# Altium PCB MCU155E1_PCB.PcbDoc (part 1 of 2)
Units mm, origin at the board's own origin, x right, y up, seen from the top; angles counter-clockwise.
Board outline 32 x 29 mm, 4 copper layers (Top Layer, Layer 1, Layer 2, Bottom Layer), stack 1.567 mm thick; 102 components, 61 nets, 283 pads, 120 vias.
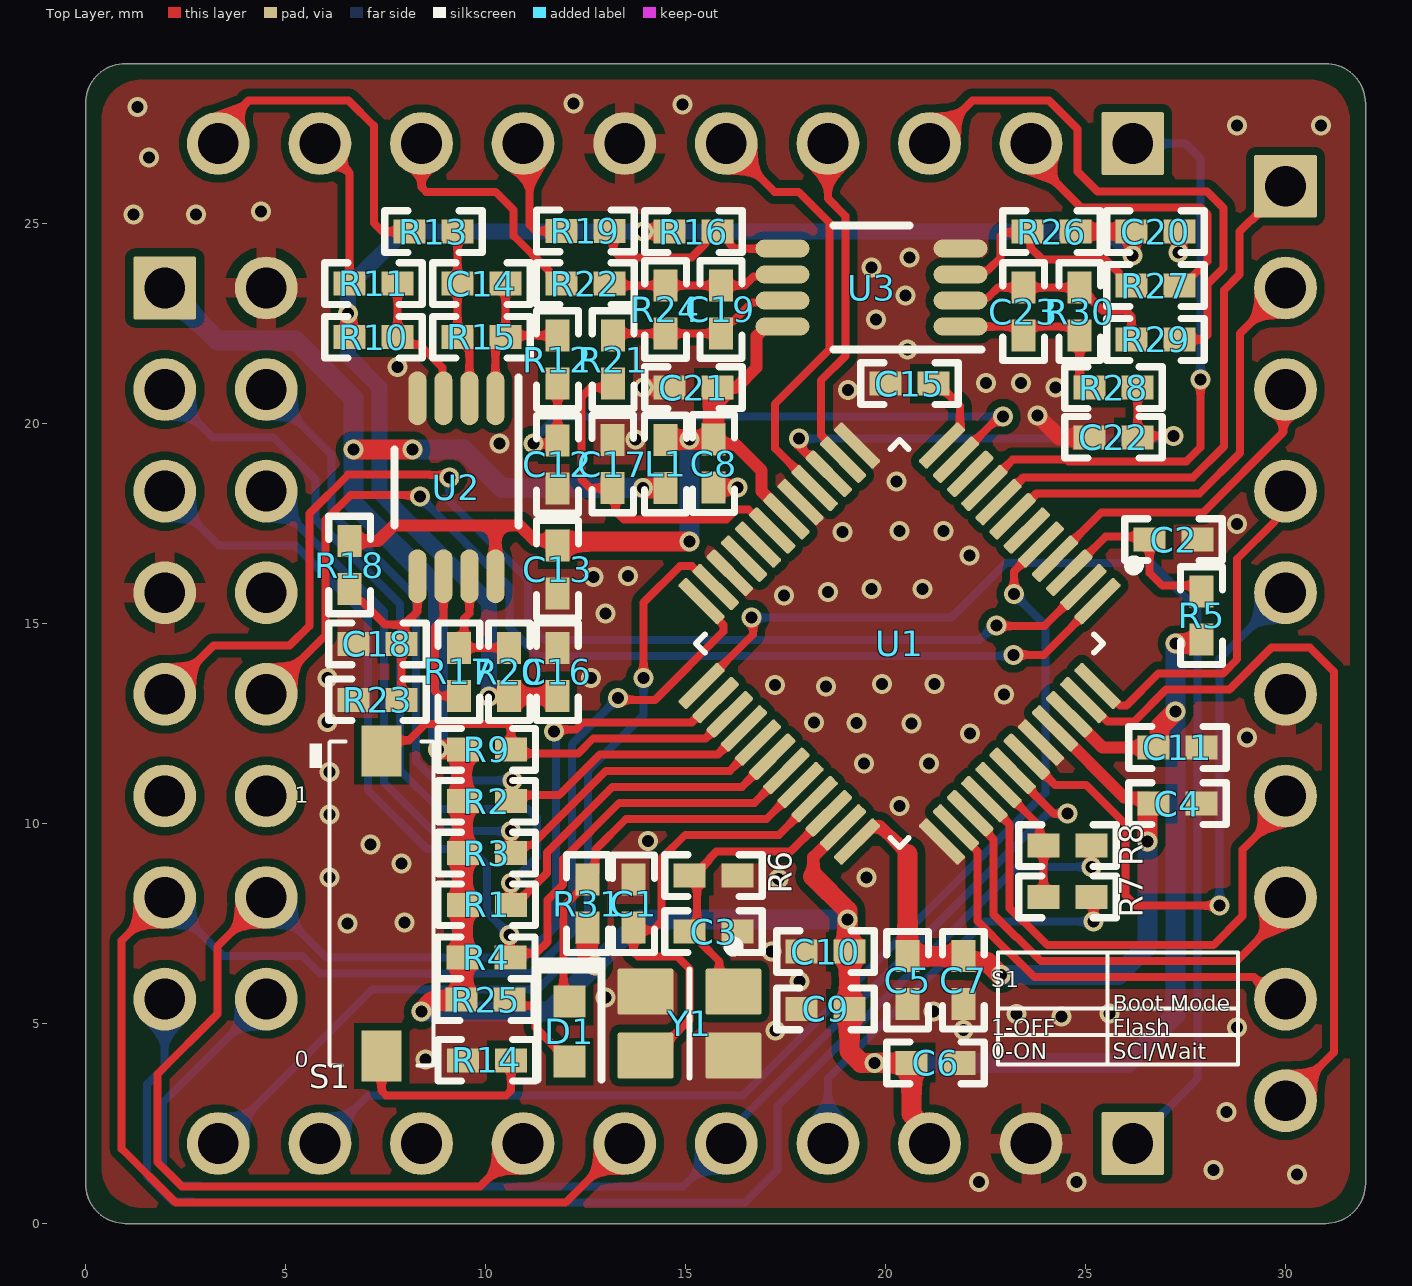
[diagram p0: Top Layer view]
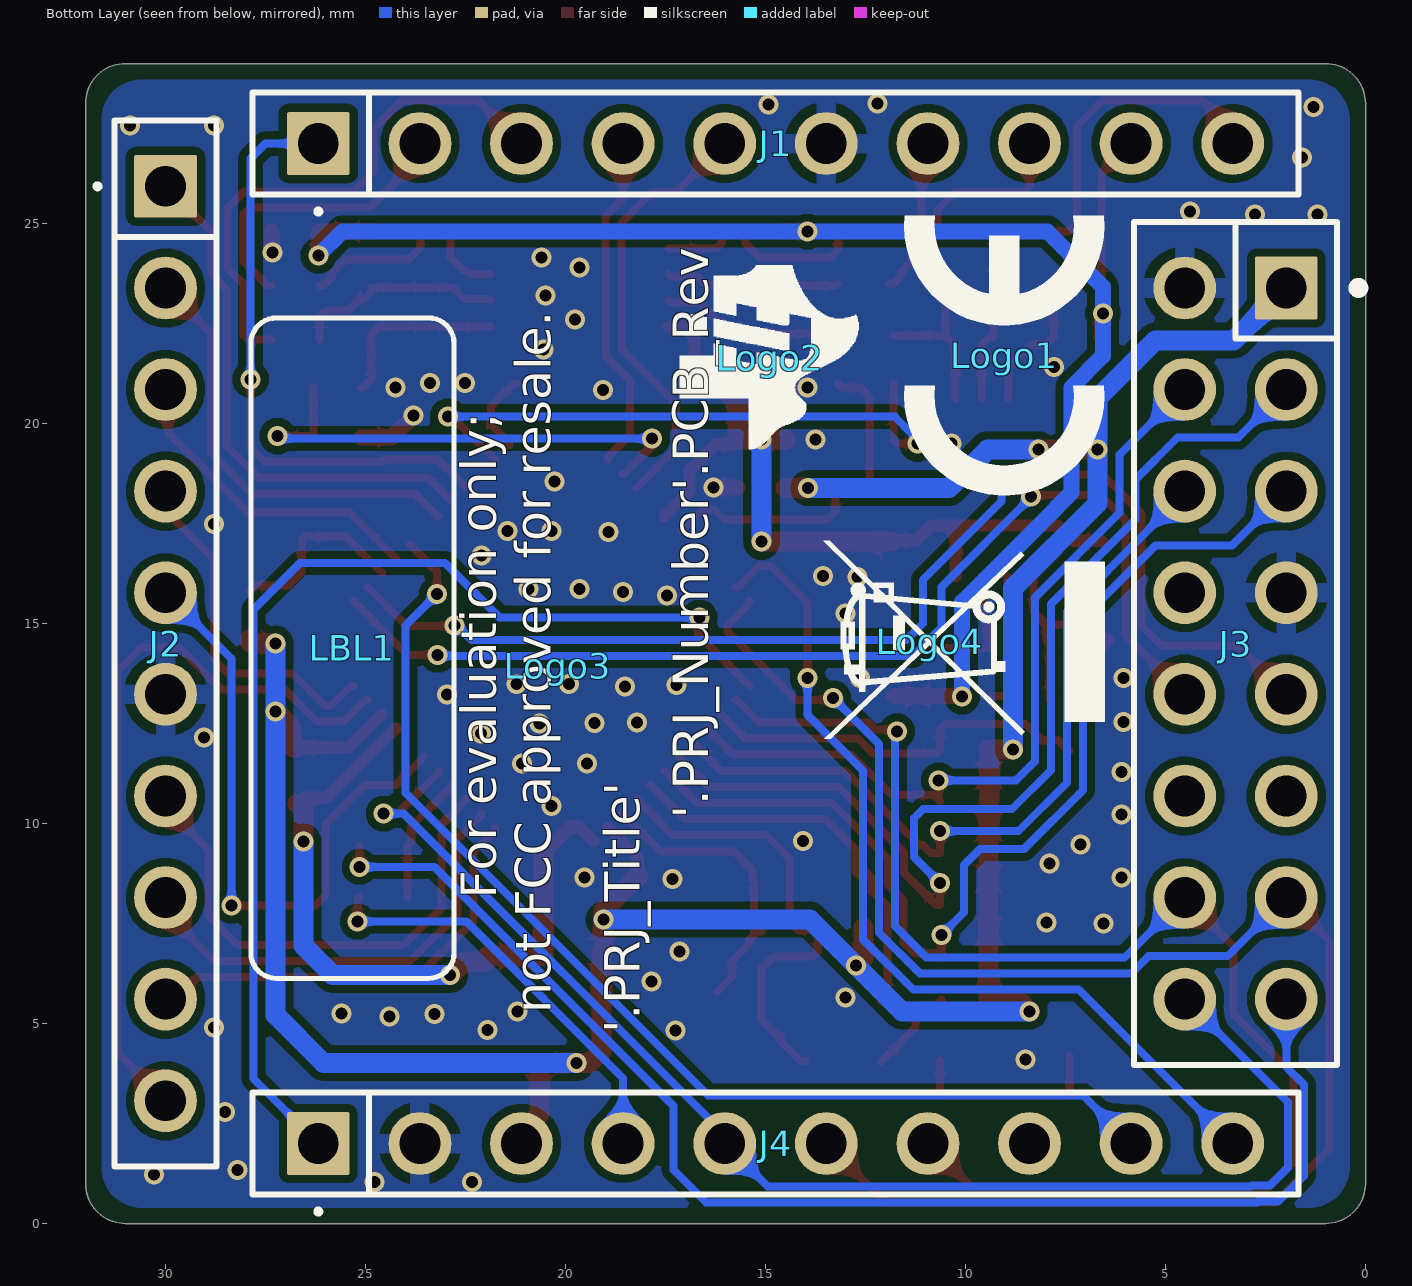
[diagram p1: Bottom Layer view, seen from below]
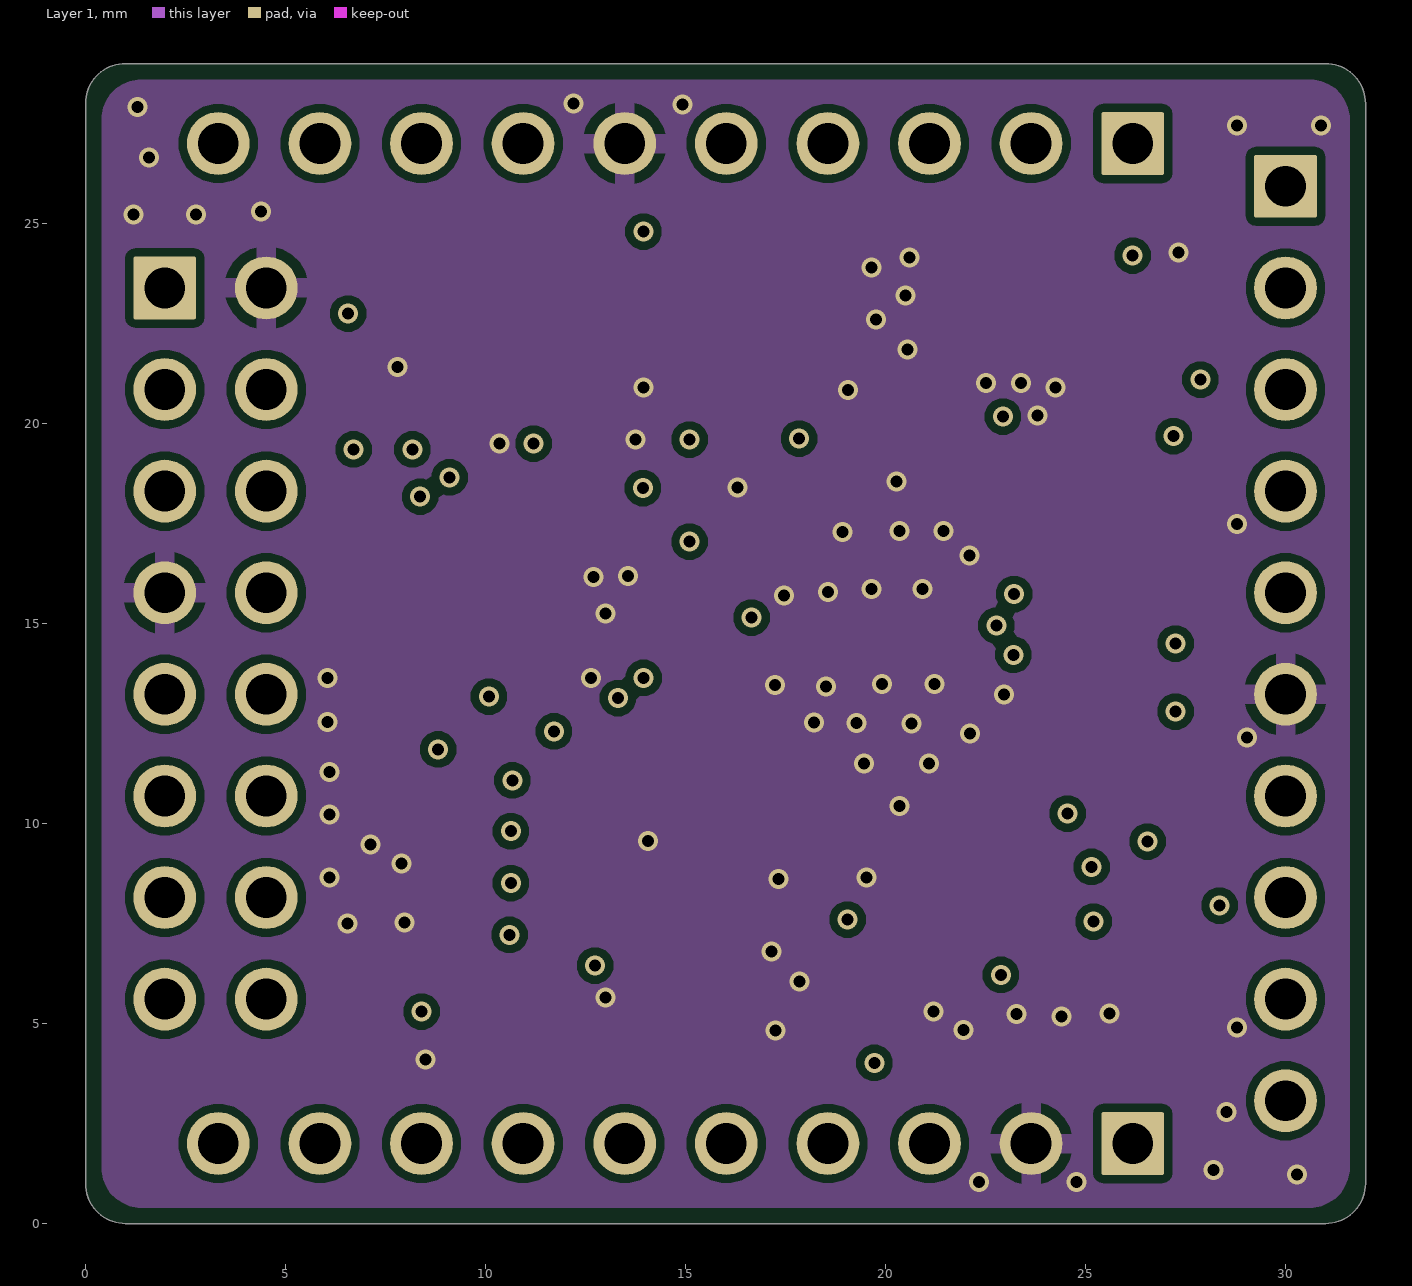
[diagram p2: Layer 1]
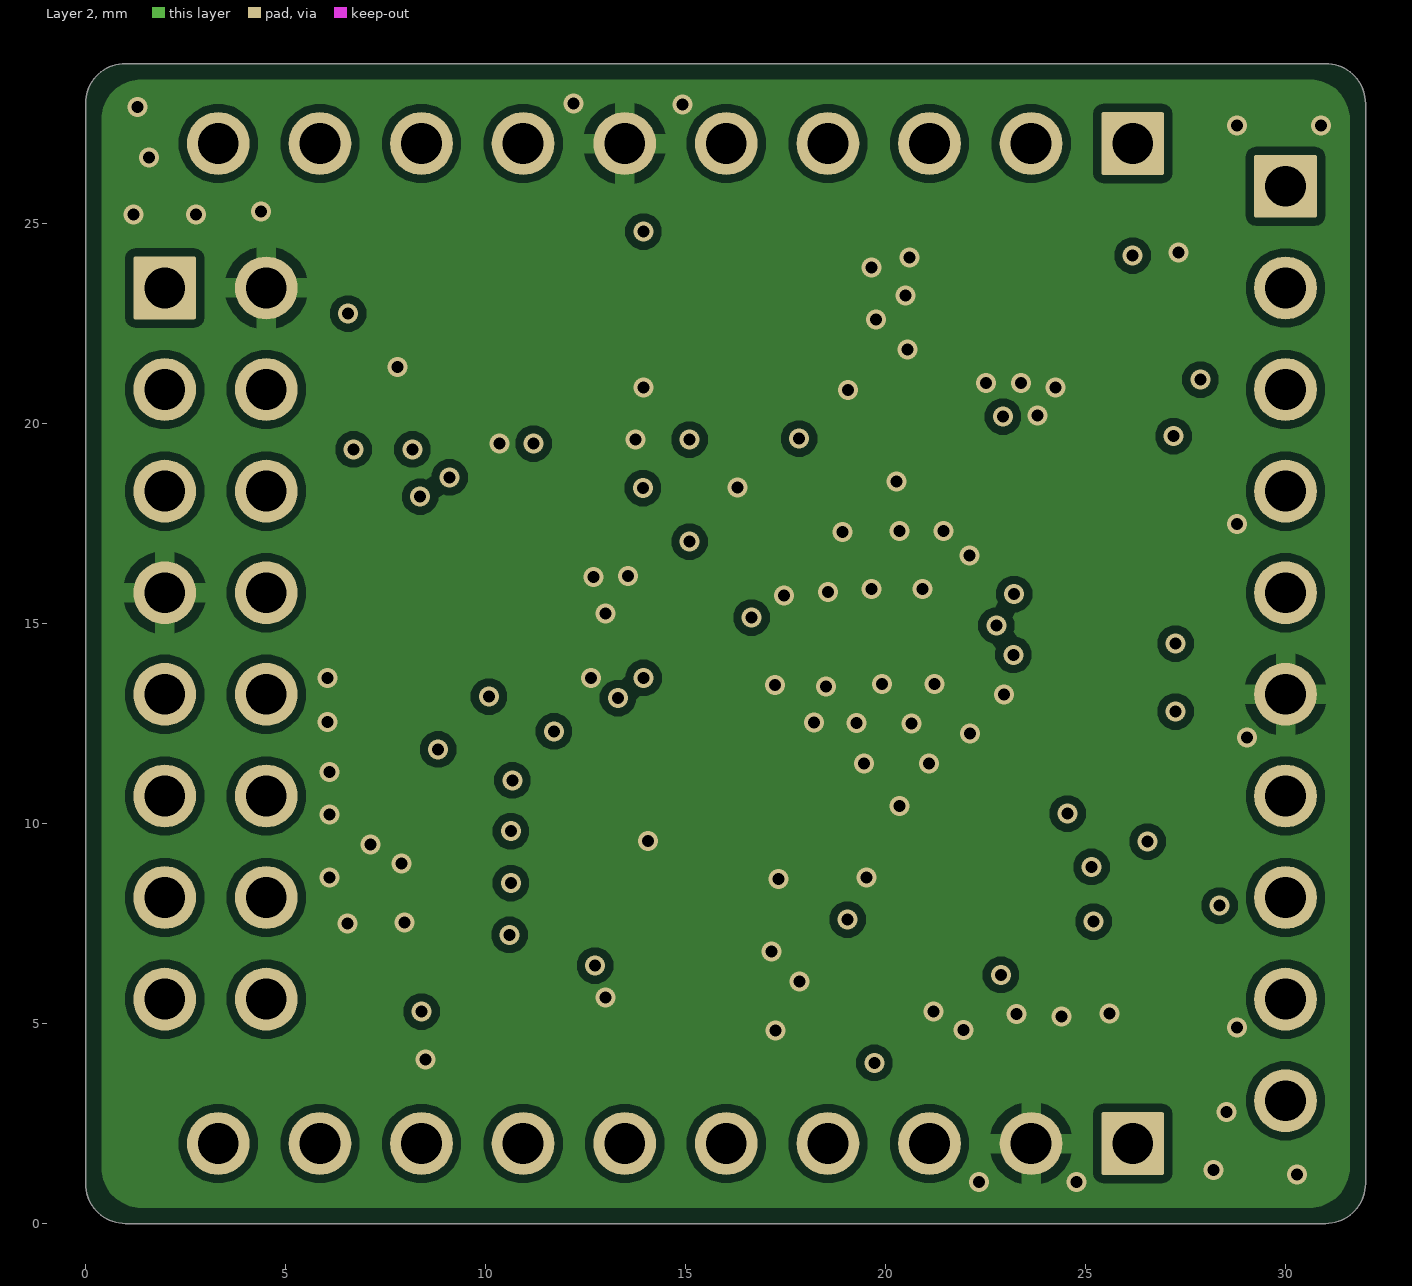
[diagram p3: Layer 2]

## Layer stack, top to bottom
Top Solder: solder mask 0.0102, Solder Resist, Dk 3.5
Top Layer: signal copper 0.035
Dielectric 1: prepreg 0.2184, PP-023, Dk 4.5
Layer 1: signal copper 0.035
Dielectric1: core 0.9906, Core-042, Dk 4.6
Layer 2: signal copper 0.035
Dielectric 2: prepreg 0.2184, PP-023, Dk 4.5
Bottom Layer: signal copper 0.035
Bottom Solder: solder mask 0.0102, Solder Resist, Dk 3.5

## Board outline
0,1 0,28 cw(c1,28) 1,29 31,29 cw(c31,28) 32,28 32,1 cw(c31,1) 31,0 1,0 cw(c1,1)

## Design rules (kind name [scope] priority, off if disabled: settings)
AcuteAngle [All] p1: minimum=4.50000000000000E+0001 checktracksonly=FALSE
AssemblyTestPointUsage [All] p1: valid=2
BoardOutlineClearance BoardOutlineClearance_MountingHoles [OnCopper and InComponentClass('Mounting Holes')] p1: gap=0 ignorepadtopadclearanceinfootprint=FALSE
BoardOutlineClearance BoardOutlineClearance_Poly [OnCopper and IsPoly] p2: gap=0 ignorepadtopadclearanceinfootprint=FALSE
BoardOutlineClearance [OnCopper and Not InComponentClass('Logo') and not InComponentClass('FiducialMark') and not InRegion(1000,500,4000,800) and not InPoly] p3: gap=0 ignorepadtopadclearanceinfootprint=FALSE
Clearance Clearance_1 [(InComponent('J1') or InComponent('J2') or InComponent('J3') or InComponent('J4') ) and not HasFootprint('fiducial10-20')] p1: gap=0.19 ignorepadtopadclearanceinfootprint=TRUE
Clearance PB+ToPB- [InNetClass('HV') vs InNetClass('LV_Signal')] p2: gap=3 ignorepadtopadclearanceinfootprint=TRUE
Clearance PB-ToACN [InNetClass('LV Signal') vs InNetClass('ACN')] p3: gap=3 ignorepadtopadclearanceinfootprint=TRUE
Clearance ACLToACN [InNetClass('ACL') vs InNetClass('ACN')] p4: gap=2 ignorepadtopadclearanceinfootprint=FALSE
Clearance ISOToAll [InNetClass('Isolation') vs not InNetClass('Isolation')   and (not  OnLayer('Keep-Out Layer'))] p5: gap=6 ignorepadtopadclearanceinfootprint=TRUE
Clearance PB-ToACL [InNetClass('LV Signal') vs InNetClass('ACL')] p6: gap=3 ignorepadtopadclearanceinfootprint=TRUE
Clearance PB+ToACL [InNetClass('V_BUS') vs InNetClass('ACL')] p7: gap=3 ignorepadtopadclearanceinfootprint=TRUE
Clearance PB+ToACN [InNetClass('V_BUS') vs InNetClass('ACN')] p8: gap=1.5 ignorepadtopadclearanceinfootprint=TRUE
Clearance SMTPadToTHHole [not IsVia and OnLayer('Multi-Layer') and not InComponent('J1') and not InComponent('J2') and not InComponent('J3') and not InComponent('J4') and not InComponent('J12') and PadIsPlated vs InSMTComponent and OnLayer('Bottom Layer') and not HasFootprint('TP_SM_1MM')] p9: gap=0.15 ignorepadtopadclearanceinfootprint=FALSE except(3: SMDPad-THPad)
Clearance [All vs not HasFootprint('fiducial10-20') or (InComponent('J1') or InComponent('J2') or InComponent('J3') or InComponent('J4') )] p10: gap=0.2 ignorepadtopadclearanceinfootprint=TRUE
ComponentClearance ComponentClearance_MountingHoles_FiducialMarks [InComponentClass('Mounting Holes') vs InComponentClass('FiducialMark')] p1: gap=1.27 collisioncheckmode=3 verticalgap=0.254 showdistances=FALSE
ComponentClearance ComponentClearance_Shunt [InComponentClass('Header') vs InComponentClass('Shunt')] p2: gap=0 collisioncheckmode=3 verticalgap=0 showdistances=FALSE
ComponentClearance ComponentClearance_Logo [InComponentClass('Logo')] p3: gap=0.762 collisioncheckmode=3 verticalgap=0.254 showdistances=FALSE
ComponentClearance ComponentClearance_ScrewToNut [(HasFootprint('NY PMS 440 0025 PH')) vs (HasFootprint('Keystone_1902C'))] p4: gap=0.127 collisioncheckmode=3 verticalgap=0.254 showdistances=FALSE
ComponentClearance ComponentClearance_MountingHoles [InComponentClass('Mounting Holes')] p5: gap=2.54 collisioncheckmode=3 verticalgap=2540 showdistances=FALSE
ComponentClearance ComponentClearance_SmallPassives [HasFootprint('0201*') or HasFootprint('0402*') or HasFootprint('0508') or HasFootprint('0603*') or HasFootprint('0612') or HasFootprint('0805*') or HasFootprint('0815*') or HasFootprint('0830*') or HasFootprint('1206*') or HasFootprint('1210*') or HasFootprint('1808*') or HasFootprint('1812*') or HasFootprint('1825*') or HasFootprint('2010*') or HasFootprint('2220*') or HasFootprint('2225*') or HasFootprint('2512*') or HasFootprint('2728*') or HasFootprint('3518*') vs HasFootprint('0201*') or HasFootprint('0402*') or HasFootprint('0508') or HasFootprint('0603*') or HasFootprint('0612') or HasFootprint('0805*') or HasFootprint('0815*') or HasFootprint('0830*') or HasFootprint('1206*') or HasFootprint('1210*') or HasFootprint('1808*') or HasFootprint('1812*') or HasFootprint('1825*') or HasFootprint('2010*') or HasFootprint('2220*') or HasFootprint('2225*') or HasFootprint('2512*') or HasFootprint('2728*') or HasFootprint('3518*')] p6: gap=0.38 collisioncheckmode=3 verticalgap=0.254 showdistances=FALSE
ComponentClearance ComponentClearance_THtoSMT [IsThruComponent vs IsSMTComponent] p7: gap=0.762 collisioncheckmode=3 verticalgap=0.762 showdistances=FALSE
ComponentClearance ComponentClearance_THtoTH [IsThruComponent vs IsThruComponent] p8: gap=0.508 collisioncheckmode=3 verticalgap=0.762 showdistances=FALSE
ComponentClearance [All] p9: gap=0.508 collisioncheckmode=3 verticalgap=0.254 showdistances=FALSE
DiffPairsRouting [All] p1: maxlimit=2.54 minlimit=0.254 mostfreqgap=0.254 toplayer_minwidth=0.381 toplayer_maxwidth=0.381 toplayer_prefwidth=0.381 midlayer1_minwidth=0.381 midlayer1_maxwidth=0.381 midlayer1_prefwidth=0.381 midlayer2_minwidth=0.381 midlayer2_maxwidth=0.381 midlayer2_prefwidth=0.381 bottomlayer_minwidth=0.381 bottomlayer_maxwidth=0.381 bottomlayer_prefwidth=0.381 maxuncoupledlength=25.4
FabricationTestPointUsage TestPointUsage [All] p1: valid=2 allowmultiple=FALSE
FabricationTestpoint Testpoint [All] p1: side=3 testpointundercomponent=TRUE minsize=1.016 maxsize=2.54 preferedsize=1.524 minholesize=0 maxholesize=1.016 preferedholesize=0.813 testpointgrid=0.025 allowsidetop=TRUE allowsidebottom=TRUE usegrid=TRUE gridtolerance=0
FanoutControl Fanout_LCC [IsLCC] p1: bgadir=Out bgaviamode=Centered fanoutstyle=Auto fanoutdirection=Alternating viagrid=0.025 // Fanout_LCC (Default Rule)
FanoutControl Fanout_BGA [IsBGA] p2: bgadir=Out bgaviamode=Centered fanoutstyle=Auto fanoutdirection=Alternating viagrid=0.025 // Fanout_BGA (Default Rule)
FanoutControl Fanout_Default [All] p4: bgadir=Out bgaviamode=Centered fanoutstyle=Auto fanoutdirection=Alternating viagrid=0.025 // Fanout_Default (Default Rule)
FanoutControl Fanout_Small [(CompPinCount < 5)] p5: bgadir=Out bgaviamode=Centered fanoutstyle=Auto fanoutdirection=OutThenIn viagrid=0.025 // Fanout_Small (Default Rule)
HoleSize [All] p1: absolutevalues=TRUE maxlimit=6.375 minlimit=0.2 maxpercent=80.000 minpercent=20.000
MinimumAnnularRing MinimumAnnularRing_ThermalPadVias [IsVia and InAnyComponent] p1: minimumring=0.15
MinimumAnnularRing [All] p2: minimumring=0.2
MinimumSolderMaskSliver MinimumSolderMaskSliver_Logo [InComponentClass('Logo') vs InComponentClass('Logo')] p1: minsoldermaskwidth=0.018
MinimumSolderMaskSliver [All] p2: minsoldermaskwidth=0.1
PlaneConnect [All] p1: planeconnectstyle=Direct reliefexpansion=0.254 reliefentries=4 reliefconductorwidth=0.254 reliefairgap=0.254
PolygonConnect "Thermal relief" [All vs InNet('GND') or innet('GND_ISO')  or innet('ubus')] p1: thpad.connectstyle=Relief thpad.reliefconductorwidth=0.5 thpad.reliefentries=4 thpad.polygonreliefangle="90 Angle" thpad.airgapwidth=0.254 smdpad.connectstyle=Direct smdpad.reliefconductorwidth=0.5 smdpad.reliefentries=4 smdpad.polygonreliefangle="90 Angle" smdpad.airgapwidth=0.254 via.connectstyle=Direct via.reliefconductorwidth=0.5 via.reliefentries=4 via.polygonreliefangle="90 Angle" via.airgapwidth=0.254
PolygonConnect [All] p2: connectstyle=Direct reliefconductorwidth=0.254 reliefentries=4 polygonreliefangle="90 Angle" airgapwidth=0.254
RoutingVias ThermalPadVias [IsVia and InAnyComponent] p1: holewidth=0.2 width=0.5 viastyle="Through Hole" minholewidth=0.2 minwidth=0.5 maxholewidth=0.33 maxwidth=0.6
RoutingVias [All] p2: holewidth=0.2 width=0.5 viastyle="Through Hole" minholewidth=0.2 minwidth=0.4 maxholewidth=1 maxwidth=1.4
SilkToBoardRegionClearance [Not ((IsComment or IsDesignator) And (Hide <> 'False')) and not InRegion(1000,500,4000,800)] p1:
SilkToSilkClearance SilkToSilkClearance_Pb-FreeLogo [(HasFootprint('Pb-Free_Overlay_Medium') OR HasFootprint('Pb-Free_Overlay_Small')) vs (HasFootprint('Pb-Free_Overlay_Medium') OR HasFootprint('Pb-Free_Overlay_Small'))] p1: silktosilkclearance=0
SilkToSilkClearance [All] p2: silktosilkclearance=0.1
SilkToSolderMaskClearance SilkToComponentPadClearance [(IsPad or IsFill or IsRegion) and InAnycomponent] p1: minsilkscreentomaskgap=0.127 clearancetoexposedcopper=TRUE
SilkToSolderMaskClearance "Silk to Solder Mask Opening" [All] p2: minsilkscreentomaskgap=0.1 clearancetoexposedcopper=FALSE
SolderMaskExpansion [All] p1: expansion=0.05 istentingtop=FALSE
UnRoutedNet [All] p1: checkbadconnections=TRUE
Width [All] p1: maxlimit=5 minlimit=0.2 preferedwidth=0.3 minimp=50.000000 maximp=50.000000 favimp=50.000000 checkconnectedcopper=TRUE
14 further rules are at their usual default settings.

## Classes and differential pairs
component class Logo: Logo2
component class Label: LBL1
component class TIEVM-MC-MODULE-F280013x: C1 C2 C3 C4 C5 C6 C7 C8 C9 C10 C11 C12 C13 C14 C15 C16 C17 C18 C19 C20 C21 C22 C23 D1 J1 J2 J3 J4 L1 LBL1 Logo1 Logo2 Logo3 Logo4 R1 R2 R3 R4 R5 R6 R7 R8 R9 R10 R11 R12 R13 R14 R15 R16 R17 R18 R19 R20 R21 R22 R23 R24 R25 R26 R27 R28 R29 R30 R31 S1 U1 U2 U3 Y1

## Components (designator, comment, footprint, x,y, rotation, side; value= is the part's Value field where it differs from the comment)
C1 "GRM1555C1H120JA01D" 0402 13.7,7.998 r270 top value=12pF
C2 "GRM155R71C104KA88D" 0402 27.2,17.1 r0 top value=0.1uF
C3 "GRM1555C1H120JA01D" 0402 15.7,7.3 r0 top value=12pF
C4 "GRM155R71C104KA88D" 0402 27.3,10.5 r180 top value=0.1uF
C5 "GRM155R71C104KA88D" 0402 20.551,6.083 r90 top value=0.1uF
C6 "GRM155R61A106ME11" 0402 21.25,4.015 r0 top value=10uF
C7 "GRM155R61A106ME11" 0402 21.948,6.083 r90 top value=10uF
C8 "GRM155R61A106ME11" 0402 15.7,19 r270 top value=10uF
C9 "GRM155R61A106ME11" 0402 18.5,5.366 r180 top value=10uF
C10 "GRM155R71C104KA88D" 0402 18.5,6.8 r180 top value=0.1uF
C11 "GRM155R71C104KA88D" 0402 27.3,11.901 r0 top value=0.1uF
C12 "C1005C0G1H221F050BA" 0402 11.8,18.977 r270 top value=220pF
C13 "GRM155R71C104KA88D" 0402 11.8,16.353 r270 top value=0.1uF
C14 "GRM1555C1H101JA01D" 0402 9.9,23.5 r0 top value=100pF
C15 "GRM155R61A225ME95" 0402 20.6,21 r180 top value=2.2uF
C16 "GRM155R61C103KA01D" 0402 11.799,13.793 r90 top value=0.01uF
C17 "C1005C0G1H221F050BA" 0402 13.18,18.988 r90 top value=220pF
C18 "GRM155R71C104KA88D" 0402 7.299,14.491 r180 top value=0.1uF
C19 "GRM1555C1H101JA01D" 0402 15.887,22.852 r270 top value=100pF
C20 "GRM155R71C104KA88D" 0402 26.75,24.8 r0 top value=0.1uF
C21 "GRM155R71C104KA88D" 0402 15.2,20.9 r180 top value=0.1uF
C22 "C1005C0G1H221F050BA" 0402 25.7,19.656 r180 top value=220pF
C23 "GRM1555C1H101JA01D" 0402 23.451,22.8 r270 top value=100pF
D1 "LTST-C193KRKT-5A" LTST-C193_Red 12.1,4.8 r90 top value=Red
J1 "SSQ-110-03-T-S" FP-SSQ-110-03-T-S_CONN_RCPT10-MFG 14.75,27 r180 bottom
J2 "SSQ-110-03-T-S" FP-SSQ-110-03-T-S_CONN_RCPT10-MFG 30,14.5 r270 bottom locked
J3 "SSQ-108-03-T-D" FP-SSQ-108-03-T-D_HDR16-MFG 3.25,14.5 r270 bottom locked
J4 "SSQ-110-03-T-S" FP-SSQ-110-03-T-S_CONN_RCPT10-MFG 14.75,2 r180 bottom locked
L1 "782423100" 0402 14.5,18.988 r90 top value="10 ohm"
LBL1 "THT-14-423-10" Label_650x200 25.326,14.385 r270 bottom
Logo1 "CE Mark" CE_Mark_5mm 9.033,21.7 r90 bottom
Logo2 "Texas Instruments" TI_Symbol_Overlay_Small 14.9,21.65 r90 bottom
Logo3 "FCC disclaimer" FCC_disclaimer_stacked 20.2,13.95 r90 bottom
Logo4 "WEEE logo" WEEE_Minimum 10.9,14.55 r90 bottom
M44 "Comment" Arrow 375.549,113.9 r0 top
M45 "Comment" Arrow 418.549,113.9 r180 bottom
M46 "Comment" MARK 448.049,-5.6 r0 top
M47 "Comment" Toolinghole 433.049,-7.1 r0 top
M48 "Comment" "White oil-26X4" 354.049,111.9 r0 top
M49 "Comment" "Bad Mark" 418.049,-5.6 r0 top
M49 "Comment" MARK 443.049,-5.6 r0 top
M49_1 "Comment" "Bad Mark" 386.049,-5.6 r0 top
M49_2 "Comment" "Bad Mark" 354.049,-5.6 r0 top
M50 "Comment" MARK 298.049,-5.6 r0 top
M51 "Comment" MARK 298.049,112.4 r0 top
M52 "Comment" MARK 448.049,112.4 r0 top
M53 "Comment" Toolinghole 308.049,-7.1 r0 top
M54 "Comment" Toolinghole 308.049,113.9 r0 top
M55 "Comment" Toolinghole 438.049,113.9 r0 top
M56 "Comment" "Bad Mark" 413.049,-5.6 r0 top
M56_1 "Comment" "Bad Mark" 381.049,-5.6 r0 top
M56_2 "Comment" "Bad Mark" 349.049,-5.6 r0 top
M57 "Comment" "Bad Mark" 408.049,-5.6 r0 top
M57_1 "Comment" "Bad Mark" 376.049,-5.6 r0 top
M57_2 "Comment" "Bad Mark" 344.049,-5.6 r0 top
M57_2_1 "Comment" "Bad Mark" 334.049,-5.6 r0 top
M57_2_2 "Comment" "Bad Mark" 322.049,-5.6 r0 top
M58 "Comment" "Bad Mark" 403.049,-5.6 r0 top
M58_1 "Comment" "Bad Mark" 371.049,-5.6 r0 top
M58_2 "Comment" "Bad Mark" 339.049,-5.6 r0 top
M58_2_1 "Comment" "Bad Mark" 329.049,-5.6 r0 top
M59 "Comment" "Bad Mark" 398.049,-5.6 r0 top
M59_1 "Comment" "Bad Mark" 366.049,-5.6 r0 top
M60 "Comment" "Bad Mark" 393.049,-5.6 r0 top
M60_1 "Comment" "Bad Mark" 361.049,-5.6 r0 top
M61 "Comment" "Bad Mark" 425.049,-5.6 r0 top
R1 "ERJ-2RKF2401X" 0402 10.035,7.967 r180 top value=2.40k
R2 "RC0402FR-0710KL" 0402 10.035,10.557 r180 top value=10.0k
R3 "RC0402FR-0710KL" 0402 10.035,9.262 r180 top value=10.0k
R4 "RC0402FR-0710KL" 0402 10.019,6.647 r180 top value=10.0k
R5 "RC0402FR-0710KL" 0402 27.9,15.2 r270 top value=10.0k
R6 "RG1005P-104-B-T5" 0402 15.7,8.698 r180 top value=100k
R7 "RC0402JR-070RL" 0402 24.55,8.166 r180 top value=0
R8 "RC0402JR-070RL" 0402 24.55,9.45 r180 top value=0
R9 "CMP-0026949-3" 0402 10.035,11.852 r180 top value=56k
R10 "RC0402FR-0710KL" 0402 7.2,22.158 r180 top value=10.0k
R11 "ERJ-2RKF2401X" 0402 7.2,23.5 r0 top value=2.40k
R12 "RC0402FR-07100RL" 0402 11.8,21.6 r270 top value=100
R13 "ERJ-2RKF2401X" 0402 8.7,24.8 r0 top value=2.40k
R14 "CMP-0026890-5" 0402 10.035,4.082 r180 top value=2.2k
R15 "RC0402FR-0710KL" 0402 9.9,22.158 r0 top value=10.0k
R16 "RC0402FR-0710KL" 0402 15.2,24.8 r180 top value=10.0k
R17 "RC0402FR-0710KL" 0402 9.336,13.793 r270 top value=10.0k
R18 "RC0402FR-0710KL" 0402 6.6,16.463 r90 top value=10.0k
R19 "ERJ-2RKF2401X" 0402 12.498,24.814 r0 top value=2.40k
R20 "RC0402FR-07100RL" 0402 10.592,13.793 r270 top value=100
R21 "RC0402FR-07100RL" 0402 13.189,21.6 r270 top value=100
R22 "ERJ-2RKF2401X" 0402 12.498,23.5 r0 top value=2.40k
R23 "RC0402FR-0710KL" 0402 7.3,13.094 r0 top value=10.0k
R24 "RC0402FR-0710KL" 0402 14.501,22.852 r270 top value=10.0k
R25 "RC0402FR-071KL" 0402 10,5.6 r0 top value=1.00k
R26 "RC0402FR-0710KL" 0402 24.15,24.8 r0 top value=10.0k
R27 "ERJ-2RKF2401X" 0402 26.75,23.451 r180 top value=2.40k
R28 "RC0402FR-07100RL" 0402 25.7,20.9 r0 top value=100
R29 "ERJ-2RKF2401X" 0402 26.75,22.102 r180 top value=2.40k
R30 "RC0402FR-0710KL" 0402 24.853,22.8 r270 top value=10.0k
R31 "CMP-0026949-3" 0402 12.55,8 r270 top value=56k
S1 "CHS-01TB" SW_CHS-01TB 7.4,8 r0 top
U1 "F2800137PT" PT0048A-MFG 20.35,14.5 r225 top locked
U2 "TLV9062IDGKR" DGK0008A_N 9.273,18.406 r270 top
U3 "TLV9062IDGKR" DGK0008A_N 19.65,23.4 r180 top
Y1 "830108207209" FP-830108207209_SMT_CRYSTAL_3MM2_2MM5-MFG 15.1,5 r180 top

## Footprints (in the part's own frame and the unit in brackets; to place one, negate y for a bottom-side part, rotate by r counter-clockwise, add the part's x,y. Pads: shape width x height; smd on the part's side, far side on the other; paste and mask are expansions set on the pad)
0402 [mm] "0402 from SM-752 data"
  rect 0.8x0.6 smd: 1(-0.6,0) 2(0.6,0)
  silkscreen extent -1.22,-0.52 1.22,0.52, body extent -0.55,-0.3 0.55,0.3, height 0.6
Arrow [mm] "·½Ïò¼ýÍ·"
  silkscreen extent 0,-2 43,2
"Bad Mark" [mm]
  round 2 on Bottom Solder: 2(0,0)
  round 2 on Top Solder: 2(0,0)
  Top Layer pour cut-out: -1.051,0 -0.971,-0.402 -0.743,-0.743 -0.402,-0.971 0,-1.051 0,-1.051 0.402,-0.971 0.743,-0.743 0.971,-0.402 1.051,0 1.051,0 0.971,0.402 0.743,0.743 0.402,0.971 0,1.051 0,1.051 -0.402,0.971 -0.743,0.743 -0.971,0.402 -1.051,0
  Top Layer region: -0.5,-0.25 -0.5,0.25 0.5,0.25 0.5,-0.25
  Top Layer region: -0.25,0.5 0.25,0.5 0.25,-0.5 -0.25,-0.5
  Bottom Layer pour cut-out: 1.051,0 0.971,-0.402 0.743,-0.743 0.402,-0.971 0,-1.051 0,-1.051 -0.402,-0.971 -0.743,-0.743 -0.971,-0.402 -1.051,0 -1.051,0 -0.971,0.402 -0.743,0.743 -0.402,0.971 0,1.051 0,1.051 0.402,0.971 0.743,0.743 0.971,0.402 1.051,0
  Bottom Layer region: 0.25,0.5 -0.25,0.5 -0.25,-0.5 0.25,-0.5
  Bottom Layer region: 0.5,-0.25 0.5,0.25 -0.5,0.25 -0.5,-0.25
CE_Mark_5mm [mm] "Minimum text height for CE Mark"
  silkscreen extent -3.5,-2.5 3.5,2.5
DGK0008A_N [mm] "TSOP, 8-Leads, Body 3x3mm, Pitch 0.65mm, IPC Medium Density"
  oval 1.35x0.45 smd: 1(-2.225,0.975) 2(-2.225,0.325) 3(-2.225,-0.325) 4(-2.225,-0.975) 5(2.225,-0.975) 6(2.225,-0.325) 7(2.225,0.325) 8(2.225,0.975)
  silkscreen extent -2.75,-1.55 0.95,1.55, body extent -2.45,-1.5 2.45,1.5, height 0.96
FCC_disclaimer_stacked [mm]
FP-830108207209_SMT_CRYSTAL_3MM2_2MM5-MFG [mm]
  rrect9% 1.4x1.15 smd paste+0 mask+0: 1(-1.1,-0.8) 2(1.1,-0.8) 3(1.1,0.8) 4(-1.1,0.8)
  silkscreen extent -1.23,-2.05 0,1.35, body extent -1.9,-1.47 1.9,1.48, height 0.25
FP-SSQ-108-03-T-D_HDR16-MFG [mm]
  rrect6% 1.57x1.57 hole 1.02 paste+0 mask+0: 1(-8.89,1.27)
  round 1.57 hole 1.02 paste+0 mask+0: 2(-8.89,-1.27) 3(-6.35,1.27) 4(-6.35,-1.27) 5(-3.81,1.27) 6(-3.81,-1.27) 7(-1.27,1.27) 8(-1.27,-1.27) 9(1.27,1.27) 10(1.27,-1.27) 11(3.81,1.27) 12(3.81,-1.27) 13(6.35,1.27) 14(6.35,-1.27) 15(8.89,1.27) 16(8.89,-1.27)
  silkscreen extent -10.54,-2.54 10.54,3.19, body extent -10.42,-2.48 10.42,2.48, height 8.64
FP-SSQ-110-03-T-S_CONN_RCPT10-MFG [mm]
  rrect6% 1.57x1.57 hole 1.02 paste+0 mask+0: 1(-11.43,0)
  round 1.57 hole 1.02 paste+0 mask+0: 2(-8.89,0) 3(-6.35,0) 4(-3.81,0) 5(-1.27,0) 6(1.27,0) 7(3.81,0) 8(6.35,0) 9(8.89,0) 10(11.43,0)
  silkscreen extent -13.08,-1.76 13.08,1.27, body extent -12.95,-1.21 12.95,1.21, height 8.64
Label_650x200 [mil] "Thermal Transfer Label"
  round 1 on Mech14: 0(0,0)
  silkscreen extent -325,-100 325,100, body extent -325,-100 325,100, height 1
LTST-C193_Red [mm] "SMD, 2-Leads, Body1.6x0.8mm"
  rect 0.8x0.8 smd: 1(-0.75,0) 2(0.75,0)
  silkscreen extent -1.2,-0.9 1.85,0.9, body extent -0.85,-0.45 0.85,0.45, height 0.45
MARK [mm]
  round 1 smd mask+0.5: 1(0,0)
  round 1 smd far side mask+0.5: 2(0,0)
  Top Layer pour cut-out: -1.5,0 -1.386,-0.574 -1.061,-1.061 -0.574,-1.386 0,-1.5 0,-1.5 0.574,-1.386 1.061,-1.061 1.386,-0.574 1.5,0 1.5,0 1.386,0.574 1.061,1.061 0.574,1.386 0,1.5 0,1.5 -0.574,1.386 -1.061,1.061 -1.386,0.574 -1.5,0
  Bottom Layer pour cut-out: -1.5,0 -1.386,-0.574 -1.061,-1.061 -0.574,-1.386 0,-1.5 0,-1.5 0.574,-1.386 1.061,-1.061 1.386,-0.574 1.5,0 1.5,0 1.386,0.574 1.061,1.061 0.574,1.386 0,1.5 0,1.5 -0.574,1.386 -1.061,1.061 -1.386,0.574 -1.5,0
PT0048A-MFG [mm]
  rrect33% 1.4x0.3 smd paste-1000 mask+0: 1(-4.25,2.75) 2(-4.25,2.25) 3(-4.25,1.75) 4(-4.25,1.25) 5(-4.25,0.75) 6(-4.25,0.25) 7(-4.25,-0.25) 8(-4.25,-0.75) 9(-4.25,-1.25) 10(-4.25,-1.75) 11(-4.25,-2.25) 12(-4.25,-2.75) 25(4.25,-2.75) 26(4.25,-2.25) 27(4.25,-1.75) 28(4.25,-1.25) 29(4.25,-0.75) 30(4.25,-0.25) 31(4.25,0.25) 32(4.25,0.75) 33(4.25,1.25) 34(4.25,1.75) 35(4.25,2.25) 36(4.25,2.75)
  rrect33% 0.3x1.4 smd paste-1000 mask+0: 13(-2.75,-4.25) 14(-2.25,-4.25) 15(-1.75,-4.25) 16(-1.25,-4.25) 17(-0.75,-4.25) 18(-0.25,-4.25) 19(0.25,-4.25) 20(0.75,-4.25) 21(1.25,-4.25) 22(1.75,-4.25) 23(2.25,-4.25) 24(2.75,-4.25) 37(2.75,4.25) 38(2.25,4.25) 39(1.75,4.25) 40(1.25,4.25) 41(0.75,4.25) 42(0.25,4.25) 43(-0.25,4.25) 44(-0.75,4.25) 45(-1.25,4.25) 46(-1.75,4.25) 47(-2.25,4.25) 48(-2.75,4.25)
  silkscreen extent -5.65,-3.6 3.6,3.6, body extent -5.05,-5.05 5.05,5.05, height 0.25
SW_CHS-01TB [mm] "CHS Recommended footprint"
  rect 1x1.27 smd: 1(0,3.81) 2(0,-3.81)
  silkscreen extent -1.8,-4.05 1.3,4.05, body extent -1.25,-4 1.25,4, height 2.51
TI_Symbol_Overlay_Small [mm]
  silkscreen extent -2.3,-2.23 2.3,2.24
Toolinghole [mm]
  round 2 hole 2 unplated: 1(0,0)
  silkscreen extent -1.41,-1.41 1.41,1.41
WEEE_Minimum [mm] "WEEElie bin"
  silkscreen extent -2.42,-4.38 2.52,2.65
"White oil-26X4" [mm] "¶þÎ¬Âë°×ÓÍ¿ò"
  silkscreen extent -26,0 0,4

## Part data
C1 C3: library part CMP-0006415-2, "CAP, CERM, 12 pF, 50 V, +/- 5%, C0G/NP0, 0402", Cap_Case=0402, Manufacturer=MuRata, Supplier Part Number 1=14T3292, TempCo=C0G/NP0, Tolerance_%=5%, Value1=Unknown, Value2=50V, ValueDisplayed=12pF
C2 C4 C5 C10 C11 C13 C18 C20 C21: library part CMP-0006641-2, "CAP, CERM, 0.1 uF, 16 V, +/- 10%, X7R, 0402", Cap_Case=0402, Manufacturer=MuRata, Supplier Part Number 1=490-3261-1-ND, TempCo=X7R, Tolerance_%=10%, Value1=Unknown, Value2=16V, ValueDisplayed=0.1uF
C6 C7 C8 C9: library part CMP-0006564-1, "CAP, CERM, 10 uF, 10 V, +/- 20%, X5R, 0402", Cap_Case=0402, Manufacturer=MuRata, TempCo=X5R, Tolerance_%=20%, Value1=Unknown, Value2=10V, ValueDisplayed=10uF
C12 C17 C22: library part CMP-0006249-2, "CAP, CERM, 220 pF, 50 V, +/- 1%, C0G/NP0, 0402", Cap_Case=0402, Manufacturer=TDK, Supplier Part Number 1=445-7015-1-ND, TempCo=C0G/NP0, Tolerance_%=1%, Value1=Unknown, Value2=50V, ValueDisplayed=220pF
C14 C19 C23: library part CMP-0006410-2, "CAP, CERM, 100 pF, 50 V, +/- 5%, C0G/NP0, 0402", Cap_Case=0402, Manufacturer=MuRata, Supplier Part Number 1=81-GRM1555C1H101JA1D, TempCo=C0G/NP0, Tolerance_%=5%, Value1=Unknown, Value2=50V, ValueDisplayed=100pF
C15: library part CMP-0006571-2, "CAP, CERM, 2.2 uF, 10 V, +/- 20%, X5R, 0402", Cap_Case=0402, Manufacturer=MuRata, Supplier Part Number 1=490-10452-1-ND, TempCo=X5R, Tolerance_%=20%, Value1=Unknown, Value2=10V, ValueDisplayed=2.2uF
C16: library part CMP-0006590-2, "CAP, CERM, 0.01 uF, 16 V, +/- 10%, X5R, 0402", Cap_Case=0402, Manufacturer=MuRata, Supplier Part Number 1=GRM155R61C103KA01D-ND, TempCo=X5R, Tolerance_%=10%, Value1=Unknown, Value2=16V, ValueDisplayed=0.01uF
D1: library part CMP-0079922-3, "LED, Red, SMD", Color=Red, Manufacturer=Lite-On, Value1=W, Value2=2V
J1 J2 J4: library part CMP-0123041-2, "Conn Socket Strip SKT 10 POS 2.54mm Solder ST Top Entry Thru-Hole Bulk", Current_A=6.3A, Digikey Part Number=SAM1206-10-ND, Manufacturer=Samtec, Mouser Part Number=200-SSQ11003TS, Octopart Part Number=b25e7b5014d46d99, Operating Temperature Range="-55°C to +105°C", Voltage_V=655V
J3: library part CMP-0123022-2, "16 Position Receptacle Connector 0.100\" (2.54mm) Through Hole Tin", Current_A=6.3A, Digikey Part Number=SAM1204-08-ND, Manufacturer=Samtec, Mouser Part Number=200-SSQ10803TD, Octopart Part Number=1608df06b0e9c9cf, Operating Temperature Range="-55°C to +105°C", Voltage_V=655V
L1: library part CMP-0003274-1, "Ferrite Bead, 10 ohm @ 100 MHz, 1.5 A, 0402", Manufacturer="Wurth Elektronik", Supplier Part Number 1=732-6691-1-ND, Value1="0.03 ohm", Value2=1.5A, ValueDisplayed="10 ohm"
LBL1: library part CMP-0003625-1, "Thermal Transfer Printable Labels, 0.650\" W x 0.200\" H - 10,000 per roll", Manufacturer=Brady, Supplier Part Number 1=97C5133
Logo1: library part CMP-0074844-1
Logo2: library part CMP-0074838-1, "Texas Instrument Corporate Signature"
Logo3: library part CMP-0074847-1, "FCC_disclaimer"
Logo4: library part CMP-0074769-1
R1 R11 R13 R19 R22 R27 R29: library part CMP-0026685-1, "RES, 2.40 k, 1%, 0.1 W, AEC-Q200 Grade 0, 0402", Manufacturer=Panasonic, Power_W=100mW, Supplier Part Number 1=P2.40KLCT-ND, TempCo="100 ppm/C", Tolerance_%=1%, Value2=0.1W, Value_Code=2k40, ValueDisplayed=2.40k
R2 R3 R4 R5 R10 R15 R16 R17 R18 R23 R24 R26 R30: library part CMP-0078669-1, "RES, 10.0 k, 1%, 0.063 W, 0402", Manufacturer="Yageo America", Power_W=63mW, Supplier Part Number 1=311-10.0KLRCT-ND, TempCo="100 ppm/C", Tolerance_%=1%, Value2=0.063W, Value_Code=10k0, ValueDisplayed=10.0k
R6: library part CMP-0026815-1, "RES, 100 k, 0.1%, 0.063 W, 0402", Manufacturer="Susumu Co Ltd", Power_W=63mW, Supplier Part Number 1=RG10P100KBCT-ND, TempCo="25 ppm/C", Tolerance_%=0.1%, Value2=0.063W, Value_Code=100k
R7 R8: library part CMP-0027004-2, "RES, 0, 5%, 0.063 W, 0402", Manufacturer="Yageo America", Power_W=63mW, Supplier Part Number 1=311-0.0JRCT-ND, TempCo="200 ppm/C", Tolerance_%=5%, Value2=0.063W, Value_Code=0000, ValueDisplayed=0
R9 R31: "RES, 56 k, 5%, 0.063 W, AEC-Q200 Grade 0, 0402", Manufacturer=Vishay-Dale, PartNumber=CRCW040256K0JNED, Power_W=63mW, Supplier Part Number 1=541-56KJCT-ND, TempCo="200 ppm/C", Tolerance_%=5%, Value2=0.063W, Value_Code=56k0, ValueDisplayed=56k
R12 R20 R21 R28: library part CMP-0026722-1, "RES, 100, 1%, 0.063 W, 0402", Manufacturer="Yageo America", Power_W=63mW, Supplier Part Number 1=311-100LRCT-ND, TempCo="100 ppm/C", Tolerance_%=1%, Value2=0.063W, Value_Code=100R, ValueDisplayed=100
R14: "RES, 2.2 k, 5%, 0.063 W, AEC-Q200 Grade 0, 0402", Manufacturer=Vishay-Dale, PartNumber=CRCW04022K20JNED, Power_W=63mW, Supplier Part Number 1=541-2.2KJCT-ND, TempCo="200 ppm/C", Tolerance_%=5%, Value2=0.063W, Value_Code=2k20, ValueDisplayed=2.2k
R25: library part CMP-0026725-1, "RES, 1.00 k, 1%, 0.0625 W, 0402", Manufacturer="Yageo America", Power_W=62.5mW, Supplier Part Number 1=311-1.00KLRCT-ND, TempCo="100 ppm/C", Tolerance_%=1%, Value2=0.0625W, Value_Code=1k00, ValueDisplayed=1.00k
S1: library part CMP-0002163-2, "Switch, Slide, SPST, Top Slide, SMT", CurrentRating_mA=100A, Manufacturer="Copal Electronics", Supplier Part Number 1=563-1004-1-ND
U1: library part CMP-0096487-1, "Real-Time Microcontrollers", Frequency_Fixed=120MHz, Manufacturer="Texas Instruments", Max Supply Voltage=3.63V, Min Supply Voltage=2.8V, Operating Temperature Range="-40°C to +125°C"
U2 U3: library part CMP-0084063-1, "10-MHz, Low-Noise, RRIO, CMOS Operational Amplifier for Cost-Sensitive Systems, DGK0008A (VSSOP-8)", Alternate Manufacturer="Texas Instruments", Alternate PartNumber=TLV9062IDGKT, Operating Temperature Range="-40 to 125 C", Rating=Catalog
Y1: library part CMP-0093781-1, "20 MHz ±10ppm Crystal 8pF 50 Ohms 4-SMD, No Lead", Digikey Part Number=1923-830108207209CT-ND, Frequency Stability=20ppm, Frequency Tolerance=10ppm, Frequency_Fixed=20MHz, Load Capacitance=8pF, Manufacturer="Wurth Electronics", Mouser Part Number=710-830108207209, Operating Temperature Range="-40°C to +85°C"

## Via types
v1: diameter 0.5, hole 0.3, Top Layer to Bottom Layer, tented both sides, 120 vias

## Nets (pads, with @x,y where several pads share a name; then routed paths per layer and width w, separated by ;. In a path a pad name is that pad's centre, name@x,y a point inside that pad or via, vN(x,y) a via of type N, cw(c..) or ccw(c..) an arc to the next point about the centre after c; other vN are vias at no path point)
3.3V: C6.1 C9.1 C10.1 C11.1 J3.1 J4.3 L1.1 R1.2 R2.2 R3.2 R4.2 R5.2 R9.2 R25.1 R31.2 U1.35 U1.46 | length 76.2
  Top Layer w0.3: 18.193,8.68 18.193,9.161 U1.35@18.935,9.904 ; U1.46@24.592,12.732 25.423,11.901 C11.1@26.7,11.901
  Top Layer w0.5: v1(6.7,19.352) v1(8.174,19.352) ; v1(8.4,5.3) 8.669,5.57 9.389,5.57 9.419,5.6 9.419,10.557 9.4,10.577 9.4,11.817 R9.2@9.435,11.852 v1(8.816,11.852) ; R31.2@12.55,7.4 12.55,6.637 v1(12.737,6.45) ; v1(13.936,18.388) L1.1@14.5,18.388 ; 18.193,8.68 19.05,7.824 19.05,6.85 C10.1@19.1,6.8 C9.1@19.1,5.366 19.1,4.308 19.393,4.015 v1(19.721,4.015) C6.1@20.65,4.015 20.65,2.734 21.1,2.284 J4.3@21.1,2 ; C11.1@26.7,11.901 26.8,11.901 26.85,11.951 26.85,12.407 27.243,12.8 v1(27.25,12.8) ; v1(27.25,14.501) 27.85,14.501 27.9,14.551 R5.2@27.9,14.6
  Bottom Layer w0.5: J3.1@1.98,23.39 3.295,22.075 5.255,22.075 6.7,20.631 v1(6.7,19.352) 6.7,18 8.816,15.884 v1(8.816,11.852) ; v1(8.174,19.352) 9.444,19.352 10.408,18.388 v1(13.936,18.388) ; v1(8.4,5.3) 11.587,5.3 13.887,7.6 v1(19.05,7.6) ; v1(19.721,4.015) 26.048,4.015 27.25,5.217 v1(27.25,14.501)
A1.65V: C16.1 C20.1 R10.2 R16.2 R20.2 R26.2 | length 37.1
  Top Layer w0.4: v1(6.565,22.75) 6.582,22.733 6.582,22.175 R10.2@6.6,22.158 ; v1(10.086,13.175) 10.094,13.184 10.583,13.184 R20.2@10.592,13.193 C16.1@11.799,13.193 ; v1(13.948,24.8) R16.2@14.6,24.8 ; R26.2@24.75,24.8 C20.1@26.15,24.8 26.165,24.785 26.165,24.216 v1(26.18,24.201)
  Bottom Layer w0.4: v1(10.086,13.175) 10.086,15.533 7.707,17.912 7.707,17.924 7.35,18.281 7.35,20.906 6.565,21.691 v1(6.565,22.75) 6.565,23.415 7.95,24.8 v1(13.948,24.8) 25.58,24.8 v1(26.18,24.201)
A3.3V: C8.1 C13.1 C21.1 L1.2 R18.2 U1.18 U2.8 U3.8 | length 20.9
  Top Layer w0.3: R18.2@6.6,17.063 7.313,17.063 7.702,17.451 8.972,17.451 8.977,17.456 10.248,17.456 ; U2.8@10.248,16.181 10.248,17.456 ; C13.1@11.85,17.046 11.838,17.034 11.79,17.082 11.225,17.082 10.851,17.456 10.248,17.456 ; C8.1@15.7,19.6 15.823,19.477 16.25,19.477 16.9,18.827 16.9,18.304 U1.18@17.521,17.682 ; C21.1@15.8,20.9 16.274,20.9 16.779,21.405 16.779,22.189 17.015,22.425 U3.8@17.425,22.425
  Top Layer w0.5: C13.1@11.85,17.046 v1(15.1,17.046) ; L1.2@14.5,19.588 14.511,19.6 v1(15.1,19.6) C8.1@15.7,19.6 15.7,20.85 15.75,20.9 C21.1@15.8,20.9
  Bottom Layer w0.5: v1(15.1,17.046) v1(15.1,19.6)
BOOT_MODE: R9.1 S1.1 U1.27 | length 10
  Top Layer w0.2: S1.1@7.4,11.81 7.667,12.077 8.082,12.077 8.498,12.493 10.518,12.493 10.635,12.376 R9.1@10.635,11.852 10.734,11.753 12.316,11.753 12.694,12.131 15.506,12.131 U1.27@16.107,12.732
GND: C1.1 C2.2 C3.2 C4.1 C5.1 C6.2 C7.1 C8.2 C9.2 C10.2 C11.2 C12.2 C13.2 C15.2 C16.2 C17.2 C18.2 C20.2 C21.2 C22.2 J1.6 J2.6 J3.2 J3.7 J4.2 R6.1 R14.2 R23.1 U1.13 U1.17 U1.22 U1.37 U1.44 U2.4 U3.4 Y1.2 Y1.4 | length 3.6
  Top Layer w0.4: C18.2@6.499,14.591 6.599,14.491 C18.2@6.699,14.491 ; v1(13.95,20.9) C21.2@14.6,20.9 ; C8.2@15.7,18.4 15.702,18.403 16.297,18.403 v1(16.3,18.405) ; v1(23.8,20.2) 24.344,19.656 C22.2@25.1,19.656 ; v1(27.324,24.279) 27.337,24.292 27.337,24.787 C20.2@27.35,24.8
  other v1: 22.338,1.041 24.769,1.041 30.286,1.225 28.2,1.343 28.519,2.794 8.5,4.1 17.25,4.83 21.948,4.833 28.793,4.9 24.401,5.179 23.278,5.237 25.6,5.256 21.2,5.3 13,5.65 17.85,6.05 17.15,6.8 6.55,7.5 7.976,7.52 17.33,8.61 6.1,8.651 19.521,8.651 7.9,9 7.121,9.48 14.057,9.558 6.1,10.232 20.351,10.438 6.1,11.283 19.468,11.502 21.087,11.495 29.041,12.149 22.113,12.254 19.271,12.517 20.644,12.5 6.05,12.544 18.212,12.531 22.961,13.226 18.511,13.43 17.231,13.465 19.912,13.493 21.23,13.493 12.639,13.64 6.05,13.644 12.999,15.256 17.467,15.705 18.566,15.79 19.65,15.86 20.924,15.86 12.706,16.163 13.563,16.187 22.1,16.703 18.919,17.293 20.351,17.312 21.448,17.312 28.793,17.491 20.278,18.551 10.35,19.5 13.75,19.6 19.068,20.843 24.25,20.9 22.507,21.01 23.387,21.01 7.794,21.408 20.55,21.85 19.766,22.606 20.501,23.202 19.65,23.9 20.6,24.15 1.199,25.224 2.76,25.224 4.391,25.3 1.582,26.646 28.793,27.454 30.891,27.454 1.301,27.909 14.923,27.975 12.198,27.998
IPM_FAULT: J4.1 U1.25 | length 28.5
  Top Layer w0.2: U1.25@15.4,13.439 16.691,14.731 16.691,15.108 v1(16.65,15.15)
  Bottom Layer w0.2: v1(16.65,15.15) 21.65,15.15 23.015,16.515 26.634,16.515 27.8,15.35 27.8,3.62 J4.1@26.18,2
IU_AD: C12.1 R12.2 U1.11 | length 15.7
  Top Layer w0.2: v1(11.2,19.5) 11.723,19.5 C12.1@11.8,19.577 R12.2@11.8,21 ; U1.11@21.764,19.096 22.782,20.114 22.879,20.114 v1(22.937,20.171)
  Bottom Layer w0.2: v1(11.2,19.5) 11.2,19.581 11.337,19.718 11.337,19.741 11.767,20.171 v1(22.937,20.171)
IU_N: J1.10 R13.1 | length 8.2
  Top Layer w0.2: J1.10@3.32,27 3.32,27.32 4.075,28.075 6.577,28.075 7.207,27.445 7.207,25.014 7.421,24.8 R13.1@8.1,24.8
IU_P: J1.9 R11.1 | length 3.8
  Top Layer w0.2: J1.9@5.86,27 6.6,26.26 R11.1@6.6,23.5
IV_AD: C17.1 R21.2 U1.19 | length 8.7
  Top Layer w0.2: R21.2@13.189,21 13.089,20.9 12.639,20.9 12.4,20.661 12.4,18.599 12.61,18.388 C17.1@13.18,18.388 13.253,18.316 13.253,17.806 13.463,17.596 16.021,17.596 16.28,17.855 16.57,17.855 U1.19@17.097,17.328
IV_N: J1.8 R22.1 | length 6
  Top Layer w0.2: J1.8@8.4,27 8.4,25.911 8.517,25.794 10.253,25.794 10.705,25.342 10.705,24.693 11.598,23.8 11.598,23.7 11.798,23.5 R22.1@11.898,23.5
IV_P: J1.7 R19.1 | length 3
  Top Layer w0.2: J1.7@10.94,27 11.105,26.835 11.105,24.958 11.248,24.814 R19.1@11.898,24.814
IW_AD: C22.1 R28.2 U1.15 | length 12.8
  Top Layer w0.2: v1(17.839,19.621) 17.897,19.564 17.897,19.38 18.534,18.743 U1.15@18.582,18.743 ; R28.2@26.3,20.9 C22.1@26.3,19.656 26.329,19.685 v1(27.2,19.685)
  Bottom Layer w0.2: v1(17.839,19.621) 27.055,19.621 27.118,19.685 v1(27.2,19.685)
IW_N: J1.3 R29.1 | length 13.6
  Top Layer w0.2: J1.3@21.1,27 22.175,28.075 24.085,28.075 24.8,27.36 24.8,26.3 25.299,25.8 28.04,25.8 28.45,25.39 28.45,23.891 28.05,23.491 28.05,22.219 27.933,22.102 R29.1@27.35,22.102
IW_P: J1.2 R27.1 | length 7.5
  Top Layer w0.2: J1.2@23.64,27 23.64,26.646 24.886,25.4 25.625,25.4 26.674,25.4 27.874,25.4 28.05,25.224 28.05,24.056 27.65,23.656 27.65,23.651 27.45,23.451 R27.1@27.35,23.451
